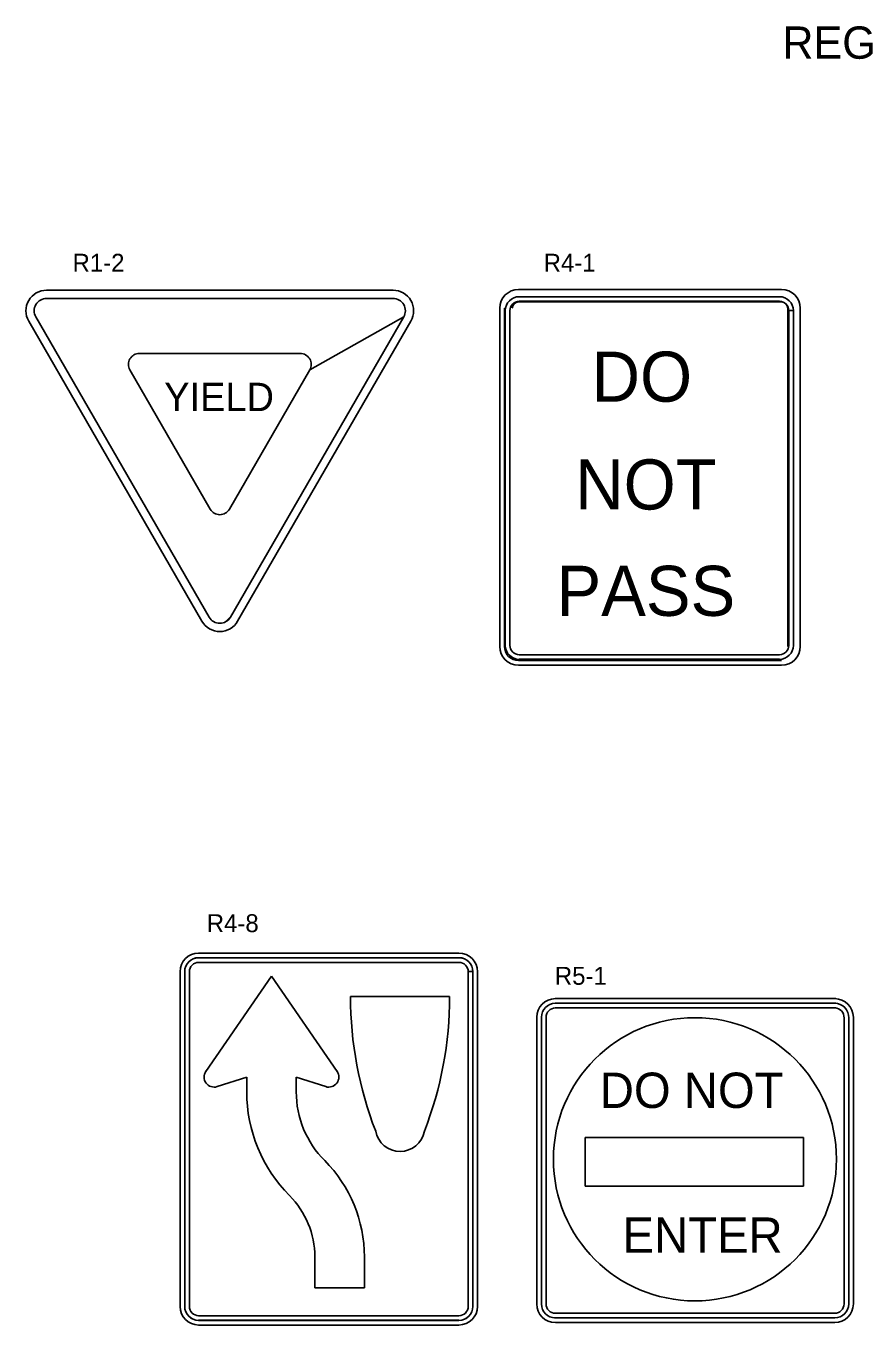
# Model space of a CAD drawing. Extents: x 1531.6 to 1538.58, y 1529.59 to 1539.33.
# Drawn here: x 1531.601 to 1534.427, y 1534.985 to 1539.332 of the extents above; entities that cross this region are included whole.
import ezdxf

# ---------------------------------------------------------------- set-up
doc = ezdxf.new("R2010")
doc.units = 0
for name, color, linetype in [('DETL-LINE', 7, 'Continuous'), ('DETL-NOTE', 7, 'Continuous'), ('DETL-TITL', 7, 'Continuous')]:
    doc.layers.add(name, color=color, linetype=linetype)

msp = doc.modelspace()

# ---------------------------------------------------------------- linework, layer by layer
at = {"layer": 'DETL-LINE'}
for p, q in [((1531.6392, 1538.4063), (1531.6424, 1538.4096)), ((1532.2498, 1538.4478), (1531.67, 1538.4478)), ((1531.67, 1538.4201), (1532.2498, 1538.4201)), ((1532.2498, 1538.4478), (1532.8297, 1538.4478)), ((1532.2498, 1538.4201), (1532.8297, 1538.4201)), ((1532.8297, 1538.4201), (1532.8297, 1538.4201)), ((1534.1303, 1538.4501), (1533.25, 1538.4501)), ((1534.1303, 1538.4082), (1533.25, 1538.4082)), ((1533.2522, 1538.426), (1534.1234, 1538.426)), ((1534.1234, 1538.4104), (1533.2522, 1538.4104)), ((1533.1872, 1538.3873), (1533.1872, 1537.2555)), ((1533.2028, 1538.3873), (1533.2028, 1537.2555)), ((1533.2056, 1537.2591), (1533.2056, 1538.3793)), ((1533.2211, 1538.3793), (1533.2211, 1537.2591)), ((1534.1513, 1537.2555), (1534.1513, 1538.3873)), ((1534.1546, 1537.2591), (1534.1546, 1538.3793)), ((1534.1546, 1538.3793), (1534.1702, 1538.3793)), ((1534.1702, 1538.3793), (1534.1702, 1537.2591)), ((1534.1932, 1537.2555), (1534.1932, 1538.3873)), ((1532.1901, 1537.3399), (1531.6102, 1538.3442)), ((1532.214, 1537.3537), (1531.6342, 1538.3581)), ((1532.8656, 1538.3581), (1532.2858, 1537.3537)), ((1532.8894, 1538.3442), (1532.3096, 1537.3399)), ((1532.8656, 1538.3581), (1532.5508, 1538.1809)), ((1532.2498, 1538.2361), (1531.9808, 1538.2361)), ((1532.5189, 1538.2361), (1532.2498, 1538.2361)), ((1531.9489, 1538.1809), (1532.218, 1537.7149)), ((1532.2818, 1537.7149), (1532.5508, 1538.1809)), ((1532.2687, 1537.3376), (1532.2868, 1537.3557)), ((1533.25, 1537.2083), (1534.1303, 1537.2083)), ((1533.25, 1537.1926), (1534.1303, 1537.1926)), ((1533.2522, 1537.228), (1534.1234, 1537.228)), ((1534.1234, 1537.2125), (1533.2522, 1537.2125)), ((1532.179, 1536.214), (1533.0503, 1536.214)), ((1533.0503, 1536.1983), (1532.179, 1536.1983)), ((1532.1791, 1536.2295), (1533.0503, 1536.2295)), ((1532.1791, 1536.2139), (1533.0503, 1536.2139)), ((1532.1791, 1536.1983), (1533.0503, 1536.1983)), ((1532.1168, 1535.047), (1532.1168, 1536.1672)), ((1532.1324, 1535.0471), (1532.1324, 1536.1673)), ((1532.1324, 1535.047), (1532.1324, 1536.1672)), ((1532.1479, 1536.1673), (1532.1479, 1535.0471)), ((1532.1479, 1535.047), (1532.1479, 1536.1672)), ((1532.4228, 1536.1517), (1532.2031, 1535.8337)), ((1532.6425, 1535.8337), (1532.4228, 1536.1517)), ((1533.0814, 1535.0471), (1533.0814, 1536.1673)), ((1533.0814, 1536.1673), (1533.097, 1536.1673)), ((1533.0814, 1536.1672), (1533.0814, 1535.047)), ((1533.097, 1536.1673), (1533.097, 1535.0471)), ((1533.097, 1536.1672), (1533.097, 1535.047)), ((1533.1125, 1536.1672), (1533.1125, 1535.047)), ((1533.0192, 1536.0842), (1532.6873, 1536.0842)), ((1533.0192, 1536.0843), (1533.0192, 1536.0842)), ((1533.3724, 1536.0769), (1534.3124, 1536.0769)), ((1534.3124, 1536.0613), (1533.3724, 1536.0613)), ((1533.3724, 1536.0459), (1534.3124, 1536.0459)), ((1533.311, 1535.9495), (1533.311, 1536.0153)), ((1533.3266, 1535.9495), (1533.3266, 1536.0147)), ((1533.3421, 1535.9495), (1533.3421, 1536.0147)), ((1534.3397, 1536.0139), (1534.3397, 1535.9495)), ((1534.3552, 1535.9495), (1534.3552, 1536.0139)), ((1534.3552, 1536.0139), (1534.3552, 1536.0123)), ((1534.3708, 1536.0139), (1534.3708, 1535.9495)), ((1533.311, 1535.0552), (1533.311, 1535.9495)), ((1533.3266, 1535.9495), (1533.3266, 1535.0552)), ((1533.3421, 1535.0552), (1533.3421, 1535.9495)), ((1534.3397, 1535.9495), (1534.3397, 1535.0552)), ((1534.3552, 1535.0552), (1534.3552, 1535.9495)), ((1534.3708, 1535.9495), (1534.3708, 1535.0552)), ((1532.2412, 1535.7825), (1532.3398, 1535.814)), ((1532.3398, 1535.814), (1532.3398, 1535.7653)), ((1532.5058, 1535.7653), (1532.5058, 1535.814)), ((1532.5058, 1535.814), (1532.6044, 1535.7825)), ((1532.6424, 1535.8337), (1532.6425, 1535.8337)), ((1533.4733, 1535.6121), (1534.2033, 1535.6121)), ((1533.4733, 1535.4498), (1533.4733, 1535.6121)), ((1534.2033, 1535.6121), (1534.2033, 1535.4498)), ((1534.2033, 1535.4498), (1533.4733, 1535.4498)), ((1532.5678, 1535.213), (1532.5678, 1535.1093)), ((1532.7338, 1535.1093), (1532.7338, 1535.213)), ((1532.5678, 1535.1093), (1532.7338, 1535.1093)), ((1534.3099, 1535.024), (1533.3699, 1535.024)), ((1534.3099, 1535.0248), (1534.3099, 1535.0253)), ((1532.179, 1535.016), (1533.0503, 1535.016)), ((1533.0503, 1535.0005), (1532.179, 1535.0005)), ((1533.0503, 1535.0159), (1532.1791, 1535.0159)), ((1533.0503, 1535.0004), (1532.1791, 1535.0004)), ((1533.0503, 1534.9848), (1532.1791, 1534.9848)), ((1533.3699, 1535.0085), (1534.3086, 1535.0085)), ((1534.3086, 1534.9929), (1533.3732, 1534.9929))]:
    msp.add_line(p, q, dxfattribs=at)
msp.add_circle((1533.8404, 1535.5394), 0.4738, dxfattribs=at)
for centre, radius, start, end in [((1531.67, 1538.3787), 0.069, 90, 210), ((1531.67, 1538.3787), 0.0414, 90, 210), ((1532.8297, 1538.3787), 0.069, 330, 90), ((1532.8297, 1538.3787), 0.0414, 330, 90), ((1533.25, 1538.3872), 0.0629, 90, 180), ((1533.2522, 1538.3793), 0.0467, 90, 180), ((1533.2522, 1538.3793), 0.0311, 90, 180), ((1533.25, 1538.3872), 0.021, 90, 180), ((1534.1234, 1538.3793), 0.0467, 0, 90), ((1534.1234, 1538.3793), 0.0311, 0, 90), ((1534.1303, 1538.3872), 0.0629, 0, 90), ((1534.1303, 1538.3872), 0.021, 0, 90), ((1531.9808, 1538.1993), 0.0368, 90, 210), ((1532.5189, 1538.1993), 0.0368, 330, 90), ((1532.2499, 1537.7333), 0.0368, 210, 330), ((1532.2499, 1537.3744), 0.069, 210, 330), ((1532.2499, 1537.3744), 0.0414, 210, 330), ((1533.25, 1537.2554), 0.0629, 180, 270), ((1533.25, 1537.2554), 0.0472, 180, 270), ((1533.2522, 1537.2591), 0.0467, 180, 270), ((1533.2522, 1537.2591), 0.0311, 180, 270), ((1534.1234, 1537.2591), 0.0467, 270, 0), ((1534.1234, 1537.2591), 0.0311, 270, 0), ((1534.1303, 1537.2554), 0.0629, 270, 0), ((1532.1791, 1536.1672), 0.0622, 90, 180), ((1532.1791, 1536.1673), 0.0467, 90, 180), ((1532.1791, 1536.1672), 0.0467, 90, 180), ((1532.1791, 1536.1673), 0.0311, 90, 180), ((1532.1791, 1536.1672), 0.0311, 90, 180), ((1533.0503, 1536.1672), 0.0622, 0, 90), ((1533.0503, 1536.1673), 0.0467, 0, 90), ((1533.0503, 1536.1672), 0.0467, 0, 90), ((1533.0503, 1536.1673), 0.0311, 0, 90), ((1533.0503, 1536.1672), 0.0311, 0, 90), ((1533.932, 1536.0839), 1.2447, 179.9823, 201.2203), ((1531.7746, 1536.0839), 1.2447, 338.7797, 0.0177), ((1533.3732, 1536.0147), 0.0622, 90, 180), ((1533.3732, 1536.0147), 0.0467, 90, 180), ((1534.3085, 1536.0147), 0.0622, 0, 90), ((1534.3085, 1536.0147), 0.0467, 357.008, 90), ((1533.3732, 1536.0147), 0.0311, 90, 180), ((1534.3085, 1536.0147), 0.0311, 355.5094, 90), ((1532.2309, 1535.8146), 0.0337, 145.3645, 287.7219), ((1532.6147, 1535.8146), 0.0337, 252.2781, 34.6355), ((1532.8324, 1535.7653), 0.4925, 180, 224.8658), ((1532.8324, 1535.7653), 0.3266, 180, 224.8658), ((1532.8533, 1535.6486), 0.083, 190.6013, 349.3987), ((1532.2775, 1535.213), 0.4564, 0, 44.8658), ((1532.2775, 1535.213), 0.2904, 0, 44.8658), ((1532.1791, 1535.047), 0.0622, 180, 270), ((1532.1791, 1535.047), 0.0467, 180, 270), ((1532.1791, 1535.0471), 0.0467, 180, 270), ((1532.1791, 1535.047), 0.0311, 180, 270), ((1532.1791, 1535.047), 0.0311, 180, 270), ((1533.0503, 1535.0471), 0.0467, 270, 0), ((1533.0503, 1535.0471), 0.0311, 270, 0), ((1533.0503, 1535.047), 0.0311, 270, 0), ((1533.0503, 1535.047), 0.0467, 270, 0), ((1533.0503, 1535.047), 0.0622, 270, 0), ((1533.3732, 1535.0552), 0.0622, 180, 270), ((1533.3732, 1535.0552), 0.0467, 180, 270), ((1533.3732, 1535.0552), 0.0311, 180, 270), ((1534.3085, 1535.0552), 0.0622, 270, 0), ((1534.3085, 1535.0552), 0.0311, 270, 0), ((1534.3085, 1535.0552), 0.0467, 270, 0)]:
    msp.add_arc(centre, radius, start, end, dxfattribs=at)

# ---------------------------------------------------------------- texts
for s, height, p in [('DO', 0.16767, (1533.4947, 1538.0745)), ('YIELD', 0.09507, (1532.0637, 1538.043)), ('NOT', 0.16767, (1533.4398, 1537.7138)), ('PASS', 0.16767, (1533.3771, 1537.3578)), ('DO NOT', 0.11829, (1533.5219, 1535.7111)), ('ENTER', 0.11829, (1533.598, 1535.2265))]:
    msp.add_text(s, height=height, dxfattribs=at).set_placement(p)
at = {"layer": 'DETL-NOTE'}
for s, p in [('R1-2', (1531.7569, 1538.5095)), ('R4-1', (1533.334, 1538.5095)), ('R4-8', (1532.2062, 1536.2995)), ('R5-1', (1533.3715, 1536.1233))]:
    msp.add_text(s, height=0.06, dxfattribs=at).set_placement(p)
at = {"layer": 'DETL-TITL'}
msp.add_text('REGULATORY SIGNS', height=0.108, dxfattribs=at).set_placement((1534.1329, 1539.2222))

doc.saveas('drawing.dxf')
